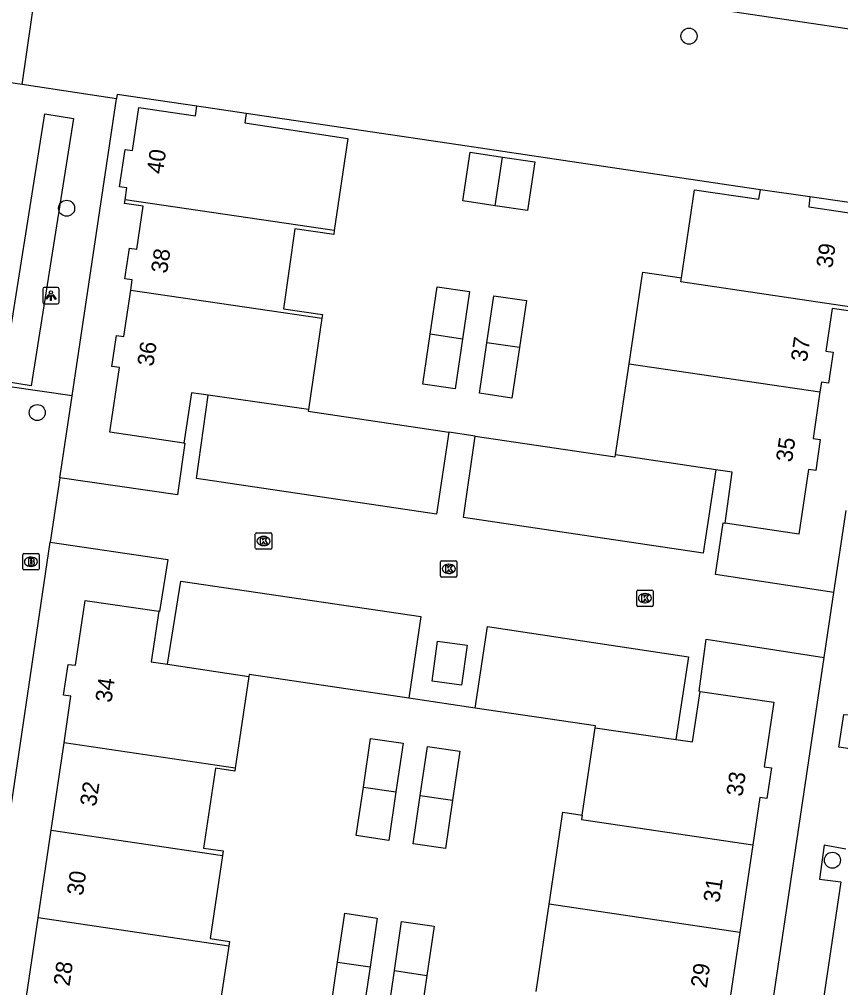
# Model space of a CAD drawing. Extents: x 164150 to 165261, y 382513 to 383432.
# Drawn here: x 164289.3 to 164339.4, y 382994.8 to 383053.9 of the extents above; entities that cross this region are included whole.
import ezdxf

# ---------------------------------------------------------------- set-up
doc = ezdxf.new("R2010")
doc.units = 0
for name, color, linetype in [('IMGEO_Boom', 7, 'Continuous'), ('IMGEO_Brandkraan', 7, 'Continuous'), ('IMGEO_Fietspad_gesloten', 7, 'Continuous'), ('IMGEO_Fietspad_open', 7, 'Continuous'), ('IMGEO_Groenvoorziening', 7, 'Continuous'), ('IMGEO_Kolk', 7, 'Continuous'), ('IMGEO_Lage_trafo', 7, 'Continuous'), ('IMGEO_Lichtpunt', 7, 'Continuous'), ('IMGEO_Pand', 7, 'Continuous'), ('IMGEO_Pand_nummerreeks', 7, 'Continuous'), ('IMGEO_Parkeervlak_open', 7, 'Continuous'), ('IMGEO_Rijbaan_lokaal_open', 7, 'Continuous'), ('IMGEO_Voetpad_open', 7, 'Continuous')]:
    doc.layers.add(name, color=color, linetype=linetype)

msp = doc.modelspace()

# ---------------------------------------------------------------- linework, layer by layer
at = {"layer": 'IMGEO_Boom'}
for centre in [(164330.143, 383052.86), (164292.167, 383042.363), (164290.373, 383029.895), (164338.896, 383002.583)]:
    msp.add_circle(centre, 0.489, dxfattribs=at)
at = {"layer": 'IMGEO_Brandkraan'}
for p, q in [((164289.488, 383020.369), (164289.488, 383021.221)), ((164289.563, 383021.295), (164290.415, 383021.295)), ((164289.976, 383021.075), (164290.001, 383021.075)), ((164290.489, 383021.221), (164290.489, 383020.369)), ((164290.415, 383020.295), (164289.563, 383020.295)), ((164289.999, 383020.515), (164289.974, 383020.515))]:
    msp.add_line(p, q, dxfattribs=at)
for points in [[(164289.488, 383020.369), (164289.488, 383021.221)], [(164289.563, 383021.295), (164290.415, 383021.295)], [(164289.836, 383020.995), (164289.836, 383020.595), (164290.049, 383020.595)], [(164290.067, 383020.995), (164289.836, 383020.995)], [(164290.015, 383020.914), (164289.961, 383020.914), (164289.961, 383020.838)], [(164290.489, 383021.221), (164290.489, 383020.369)], [(164290.415, 383020.295), (164289.563, 383020.295)], [(164289.961, 383020.838), (164290.014, 383020.838)], [(164290.023, 383020.762), (164289.961, 383020.762), (164289.961, 383020.681)], [(164289.961, 383020.681), (164290.023, 383020.681)]]:
    msp.add_lwpolyline(points, dxfattribs=at)
for centre, radius, start, end in [((164289.565, 383021.219), 0.0765, 91.55205, 178.44795), ((164289.565, 383021.219), 0.0765, 91.55205, 178.44795), ((164290.016, 383020.876), 0.0379, 267.82845, 90.93552), ((164290.071, 383020.85), 0.145, 59.4692, 91.53667), ((164290.096, 383020.897), 0.0922, 285.51372, 58.15012), ((164290.413, 383021.219), 0.0765, 1.55205, 88.44795), ((164290.413, 383021.219), 0.0765, 1.55205, 88.44795), ((164289.565, 383020.371), 0.0765, 181.55205, 268.44795), ((164289.565, 383020.371), 0.0765, 181.55205, 268.44795), ((164290.024, 383020.721), 0.0404, 269.87594, 90.50774), ((164290.055, 383020.846), 0.251, 268.66757, 293.53466), ((164290.101, 383020.705), 0.105, 301.31148, 78.98903), ((164290.413, 383020.371), 0.0765, 271.55205, 358.44795), ((164290.413, 383020.371), 0.0765, 271.55205, 358.44795)]:
    msp.add_arc(centre, radius, start, end, dxfattribs=at)
for centre, major_axis, ratio, start_param, end_param in [((164289.975, 383020.795), (-0.387, 0.002), 0.722429, 4.712389, 7.853982), ((164290, 383020.795), (-0.39, 0.002), 0.717154, 1.570796, 4.712389)]:
    msp.add_ellipse(centre, major_axis=major_axis, ratio=ratio, start_param=start_param, end_param=end_param, dxfattribs=at)
at = {"layer": 'IMGEO_Fietspad_gesloten'}
msp.add_lwpolyline([(164291.001, 383060.584), (164349.656, 383051.856)], dxfattribs=at)
at = {"layer": 'IMGEO_Fietspad_open'}
for points in [[(164289.455, 383049.901), (164290.642, 383058.11), (164290.645, 383058.127), (164291.001, 383060.584)], [(164289.455, 383049.901), (164287.476, 383050.195)]]:
    msp.add_lwpolyline(points, dxfattribs=at)
at = {"layer": 'IMGEO_Groenvoorziening'}
for points in [[(164300.119, 383048.586), (164295.247, 383049.303), (164295.212, 383049.069), (164295.209, 383049.046)], [(164334.498, 383043.494), (164333.125, 383043.698), (164321.502, 383045.42), (164316.052, 383046.228), (164303.121, 383048.144)], [(164342.411, 383042.068), (164342.452, 383042.342), (164337.518, 383043.057)]]:
    msp.add_lwpolyline(points, dxfattribs=at)
at = {"layer": 'IMGEO_Kolk'}
for p, q in [((164303.681, 383021.633), (164303.681, 383022.485)), ((164303.756, 383022.559), (164304.608, 383022.559)), ((164304.169, 383022.339), (164304.194, 383022.339)), ((164304.682, 383022.485), (164304.682, 383021.633)), ((164304.608, 383021.559), (164303.756, 383021.559)), ((164304.192, 383021.779), (164304.167, 383021.779)), ((164314.984, 383019.933), (164314.984, 383020.785)), ((164315.059, 383020.859), (164315.911, 383020.859)), ((164315.472, 383020.639), (164315.497, 383020.639)), ((164315.985, 383020.785), (164315.985, 383019.933)), ((164315.911, 383019.859), (164315.059, 383019.859)), ((164315.495, 383020.079), (164315.47, 383020.079)), ((164326.954, 383018.144), (164326.954, 383018.996)), ((164327.029, 383019.07), (164327.881, 383019.07)), ((164327.442, 383018.85), (164327.467, 383018.85)), ((164327.955, 383018.996), (164327.955, 383018.144)), ((164327.881, 383018.07), (164327.029, 383018.07)), ((164327.465, 383018.29), (164327.44, 383018.29))]:
    msp.add_line(p, q, dxfattribs=at)
for points in [[(164303.681, 383021.633), (164303.681, 383022.485)], [(164303.756, 383022.559), (164304.608, 383022.559)], [(164304.002, 383022.259), (164304.125, 383022.259), (164304.125, 383022.108), (164304.255, 383022.259), (164304.419, 383022.259), (164304.273, 383022.108), (164304.426, 383021.859), (164304.274, 383021.859), (164304.189, 383022.023), (164304.125, 383021.956), (164304.125, 383021.859), (164304.002, 383021.859), (164304.002, 383022.259)], [(164304.682, 383022.485), (164304.682, 383021.633)], [(164304.608, 383021.559), (164303.756, 383021.559)], [(164314.984, 383019.933), (164314.984, 383020.785)], [(164315.059, 383020.859), (164315.911, 383020.859)], [(164315.305, 383020.559), (164315.428, 383020.559), (164315.428, 383020.408), (164315.558, 383020.559), (164315.722, 383020.559), (164315.576, 383020.408), (164315.729, 383020.159), (164315.577, 383020.159), (164315.492, 383020.323), (164315.428, 383020.256), (164315.428, 383020.159), (164315.305, 383020.159), (164315.305, 383020.559)], [(164315.985, 383020.785), (164315.985, 383019.933)], [(164315.911, 383019.859), (164315.059, 383019.859)], [(164326.954, 383018.144), (164326.954, 383018.996)], [(164327.029, 383019.07), (164327.881, 383019.07)], [(164327.275, 383018.77), (164327.398, 383018.77), (164327.398, 383018.619), (164327.528, 383018.77), (164327.692, 383018.77), (164327.546, 383018.619), (164327.699, 383018.37), (164327.547, 383018.37), (164327.462, 383018.534), (164327.398, 383018.467), (164327.398, 383018.37), (164327.275, 383018.37), (164327.275, 383018.77)], [(164327.955, 383018.996), (164327.955, 383018.144)], [(164327.881, 383018.07), (164327.029, 383018.07)]]:
    msp.add_lwpolyline(points, dxfattribs=at)
for centre, start, end in [((164303.758, 383022.483), 91.55205, 178.44795), ((164303.758, 383022.483), 91.55205, 178.44795), ((164304.606, 383022.483), 1.55205, 88.44795), ((164304.606, 383022.483), 1.55205, 88.44795), ((164303.758, 383021.635), 181.55205, 268.44795), ((164303.758, 383021.635), 181.55205, 268.44795), ((164304.606, 383021.635), 271.55205, 358.44795), ((164304.606, 383021.635), 271.55205, 358.44795), ((164315.061, 383020.783), 91.55205, 178.44795), ((164315.061, 383020.783), 91.55205, 178.44795), ((164315.909, 383020.783), 1.55205, 88.44795), ((164315.909, 383020.783), 1.55205, 88.44795), ((164315.061, 383019.935), 181.55205, 268.44795), ((164315.061, 383019.935), 181.55205, 268.44795), ((164315.909, 383019.935), 271.55205, 358.44795), ((164315.909, 383019.935), 271.55205, 358.44795), ((164327.031, 383018.994), 91.55205, 178.44795), ((164327.031, 383018.994), 91.55205, 178.44795), ((164327.879, 383018.994), 1.55205, 88.44795), ((164327.879, 383018.994), 1.55205, 88.44795), ((164327.031, 383018.146), 181.55205, 268.44795), ((164327.031, 383018.146), 181.55205, 268.44795), ((164327.879, 383018.146), 271.55205, 358.44795), ((164327.879, 383018.146), 271.55205, 358.44795)]:
    msp.add_arc(centre, 0.0765, start, end, dxfattribs=at)
for centre, major_axis, ratio, start_param, end_param in [((164304.168, 383022.059), (-0.387, 0.002), 0.722429, 4.712389, 7.853982), ((164304.193, 383022.059), (-0.39, 0.002), 0.717154, 1.570796, 4.712389), ((164315.471, 383020.359), (-0.387, 0.002), 0.722429, 4.712389, 7.853982), ((164315.496, 383020.359), (-0.39, 0.002), 0.717154, 1.570796, 4.712389), ((164327.441, 383018.57), (-0.387, 0.002), 0.722429, 4.712389, 7.853982), ((164327.466, 383018.57), (-0.39, 0.002), 0.717154, 1.570796, 4.712389)]:
    msp.add_ellipse(centre, major_axis=major_axis, ratio=ratio, start_param=start_param, end_param=end_param, dxfattribs=at)
at = {"layer": 'IMGEO_Lage_trafo'}
msp.add_lwpolyline([(164314.788, 383015.944), (164316.601, 383015.698), (164316.264, 383013.265), (164314.465, 383013.51), (164314.788, 383015.944)], dxfattribs=at)
at = {"layer": 'IMGEO_Lichtpunt'}
for p, q in [((164290.708, 383037.431), (164290.708, 383036.624)), ((164290.708, 383037.431), (164290.708, 383036.624)), ((164291.61, 383037.526), (164290.802, 383037.526)), ((164291.61, 383037.526), (164290.802, 383037.526)), ((164291.704, 383036.624), (164291.704, 383037.431)), ((164291.704, 383036.624), (164291.704, 383037.431)), ((164290.802, 383036.53), (164291.61, 383036.53)), ((164290.802, 383036.53), (164291.61, 383036.53))]:
    msp.add_line(p, q, dxfattribs=at)
for points in [[(164291.082, 383037.095), (164291.121, 383037.067), (164290.933, 383036.805), (164290.895, 383036.832), (164291.082, 383037.095)], [(164291.184, 383037.047), (164291.231, 383037.047), (164291.231, 383036.725), (164291.184, 383036.725), (164291.184, 383037.047)], [(164291.294, 383037.067), (164291.332, 383037.094), (164291.519, 383036.832), (164291.48, 383036.804), (164291.294, 383037.067)]]:
    msp.add_lwpolyline(points, dxfattribs=at)
msp.add_circle((164291.207, 383037.229), 0.0994, dxfattribs=at)
for centre, start, end in [((164290.802, 383037.431), 90, 180), ((164290.802, 383037.431), 90, 180), ((164291.61, 383037.431), 0, 90), ((164291.61, 383037.431), 0, 90), ((164290.802, 383036.624), 180, 270), ((164290.802, 383036.624), 180, 270), ((164291.61, 383036.624), 270, 0), ((164291.61, 383036.624), 270, 360)]:
    msp.add_arc(centre, 0.0946, start, end, dxfattribs=at)
at = {"layer": 'IMGEO_Pand'}
for points in [[(164295.733, 383042.883), (164295.837, 383043.599), (164295.391, 383043.672), (164295.731, 383045.946), (164296.177, 383045.881), (164296.564, 383048.51), (164300.031, 383047.992), (164300.119, 383048.586)], [(164303.121, 383048.144), (164300.119, 383048.586)], [(164303.121, 383048.144), (164303.045, 383047.574), (164309.335, 383046.613), (164308.499, 383040.995)], [(164318.321, 383042.515), (164316.35, 383042.807), (164316.792, 383045.774), (164318.761, 383045.482)], [(164318.761, 383045.482), (164320.736, 383045.19), (164320.292, 383042.223), (164318.321, 383042.515)], [(164318.321, 383042.515), (164318.761, 383045.482)], [(164329.681, 383038.113), (164330.487, 383043.493), (164334.403, 383042.906), (164334.498, 383043.494)], [(164337.518, 383043.057), (164334.498, 383043.494)], [(164296.077, 383037.373), (164296.168, 383037.992), (164295.726, 383038.056), (164295.998, 383039.935), (164296.453, 383039.873), (164296.836, 383042.481), (164295.7, 383042.656), (164295.733, 383042.883)], [(164308.499, 383040.995), (164295.733, 383042.883)], [(164337.518, 383043.057), (164337.452, 383042.458), (164340.888, 383041.943), (164340.055, 383036.33)], [(164308.499, 383040.995), (164308.463, 383040.753), (164306.09, 383041.105), (164305.408, 383036.233), (164307.778, 383035.881), (164307.743, 383035.648)], [(164326.489, 383032.877), (164327.283, 383038.218), (164327.32, 383038.468), (164329.681, 383038.113)], [(164340.055, 383036.33), (164329.644, 383037.869), (164329.681, 383038.113)], [(164314.348, 383034.672), (164314.777, 383037.577), (164316.756, 383037.285), (164316.327, 383034.379)], [(164299.322, 383028.035), (164294.809, 383028.701), (164295.384, 383032.651), (164294.933, 383032.712), (164295.214, 383034.603), (164295.659, 383034.543), (164296.077, 383037.373)], [(164296.077, 383037.373), (164307.743, 383035.648)], [(164317.809, 383034.16), (164318.232, 383037.02), (164320.219, 383036.727), (164319.797, 383033.866)], [(164340.055, 383036.33), (164340.018, 383036.079), (164338.878, 383036.251), (164338.503, 383033.64), (164338.942, 383033.574), (164338.664, 383031.694), (164338.224, 383031.76), (164338.134, 383031.155)], [(164307.743, 383035.648), (164306.916, 383030.074)], [(164316.327, 383034.379), (164315.879, 383031.339), (164313.9, 383031.631), (164314.348, 383034.672)], [(164316.327, 383034.379), (164314.348, 383034.672)], [(164319.797, 383033.866), (164319.342, 383030.782), (164317.353, 383031.075), (164317.809, 383034.16)], [(164319.797, 383033.866), (164317.809, 383034.16)], [(164325.663, 383027.314), (164326.489, 383032.877)], [(164326.489, 383032.877), (164338.134, 383031.155)], [(164300.796, 383030.959), (164299.794, 383031.104), (164299.322, 383028.035)], [(164306.916, 383030.074), (164300.796, 383030.959)], [(164338.134, 383031.155), (164337.713, 383028.318), (164338.152, 383028.254), (164337.875, 383026.369), (164337.433, 383026.433), (164336.844, 383022.471), (164332.347, 383023.144)], [(164331.791, 383026.404), (164325.663, 383027.314)], [(164332.347, 383023.144), (164332.784, 383026.256), (164331.791, 383026.404)], [(164292.013, 383009.756), (164292.432, 383012.595), (164291.982, 383012.662), (164292.258, 383014.536), (164292.708, 383014.479), (164293.3, 383018.435), (164297.786, 383017.774)], [(164297.786, 383017.774), (164297.334, 383014.687), (164298.327, 383014.538)], [(164298.327, 383014.538), (164303.28, 383013.794)], [(164303.28, 383013.794), (164302.453, 383008.209)], [(164329.339, 383009.954), (164330.366, 383009.806), (164330.835, 383012.885)], [(164330.835, 383012.885), (164335.314, 383012.226), (164334.733, 383008.283), (164335.18, 383008.22), (164334.903, 383006.356), (164334.466, 383006.42), (164334.038, 383003.527)], [(164323.626, 383005.34), (164324.423, 383010.662)], [(164324.423, 383010.662), (164329.339, 383009.954)], [(164291.223, 383004.414), (164292.013, 383009.756)], [(164302.453, 383008.209), (164292.013, 383009.756)], [(164310.276, 383007.049), (164310.714, 383010.02), (164312.694, 383009.728), (164312.256, 383006.755)], [(164313.741, 383006.535), (164314.182, 383009.519), (164316.162, 383009.231), (164315.721, 383006.242)], [(164302.453, 383008.209), (164302.425, 383008.021), (164301.245, 383008.196), (164300.523, 383003.326), (164301.713, 383003.149), (164301.671, 383002.865)], [(164312.256, 383006.755), (164311.82, 383003.798), (164309.84, 383004.089), (164310.276, 383007.049)], [(164310.276, 383007.049), (164312.256, 383006.755)], [(164315.721, 383006.242), (164315.287, 383003.301), (164313.306, 383003.588), (164313.741, 383006.535)], [(164313.741, 383006.535), (164315.721, 383006.242)], [(164321.613, 382999.909), (164322.406, 383005.251), (164322.445, 383005.512), (164323.626, 383005.34)], [(164323.626, 383005.34), (164323.586, 383005.076), (164334.038, 383003.527)], [(164290.434, 382999.073), (164291.223, 383004.414)], [(164291.223, 383004.414), (164301.671, 383002.865)], [(164334.038, 383003.527), (164333.248, 382998.185)], [(164301.671, 383002.865), (164300.923, 382997.811), (164302.099, 382997.636), (164302.056, 382997.35)], [(164320.82, 382994.569), (164321.613, 382999.909)], [(164333.248, 382998.185), (164321.613, 382999.909)], [(164289.645, 382993.73), (164290.434, 382999.073)], [(164302.056, 382997.35), (164290.434, 382999.073)], [(164308.702, 382996.365), (164309.141, 382999.347), (164311.121, 382999.056), (164310.682, 382996.072)], [(164312.172, 382995.851), (164312.606, 382998.843), (164314.586, 382998.555), (164314.151, 382995.557)], [(164333.248, 382998.185), (164332.457, 382992.844)], [(164302.056, 382997.35), (164301.247, 382992.011)], [(164310.682, 382996.072), (164310.248, 382993.125), (164308.268, 382993.417), (164308.702, 382996.365)], [(164308.702, 382996.365), (164310.682, 382996.072)], [(164314.151, 382995.557), (164313.725, 382992.622), (164311.745, 382992.91), (164312.172, 382995.851)], [(164312.172, 382995.851), (164314.151, 382995.557)]]:
    msp.add_lwpolyline(points, dxfattribs=at)
at = {"layer": 'IMGEO_Parkeervlak_open'}
for points in [[(164306.916, 383030.074), (164306.902, 383029.983), (164315.481, 383028.705)], [(164317.098, 383028.465), (164325.645, 383027.192), (164325.663, 383027.314)], [(164313.051, 383012.471), (164303.299, 383013.923), (164303.28, 383013.794)], [(164324.423, 383010.662), (164324.44, 383010.776), (164317.096, 383011.869)]]:
    msp.add_lwpolyline(points, dxfattribs=at)
at = {"layer": 'IMGEO_Rijbaan_lokaal_open'}
for points in [[(164315.481, 383028.705), (164314.732, 383023.702), (164300.1, 383025.87), (164300.796, 383030.959)], [(164317.098, 383028.465), (164315.481, 383028.705)], [(164299.322, 383028.035), (164299.384, 383028.026), (164298.938, 383024.873), (164291.752, 383025.908)], [(164331.791, 383026.404), (164331.01, 383021.32), (164316.389, 383023.487), (164317.098, 383028.465)], [(164291.752, 383025.908), (164291.171, 383021.984)], [(164338.986, 383018.927), (164331.77, 383020.008), (164332.224, 383023.162), (164332.347, 383023.144)], [(164291.171, 383021.984), (164298.342, 383020.927), (164297.837, 383017.767), (164297.786, 383017.774)], [(164298.327, 383014.538), (164299.126, 383019.608), (164313.785, 383017.446), (164313.051, 383012.471)], [(164338.399, 383014.963), (164338.986, 383018.927)], [(164317.096, 383011.869), (164317.843, 383016.852), (164330.103, 383014.992), (164329.339, 383009.954)], [(164330.835, 383012.885), (164330.761, 383012.896), (164331.184, 383016.073), (164338.399, 383014.963)], [(164317.096, 383011.869), (164313.051, 383012.471)]]:
    msp.add_lwpolyline(points, dxfattribs=at)
at = {"layer": 'IMGEO_Voetpad_open'}
for points in [[(164295.209, 383049.046), (164289.455, 383049.901)], [(164292.499, 383030.912), (164295.209, 383049.046)], [(164290.83, 383048.121), (164292.587, 383047.843), (164290.009, 383031.53), (164288.253, 383031.807), (164290.83, 383048.121)], [(164292.499, 383030.912), (164279.108, 383032.842)], [(164291.752, 383025.908), (164291.869, 383026.7), (164292.499, 383030.912)], [(164338.986, 383018.927), (164339.726, 383023.927)], [(164278.188, 382934.213), (164291.171, 383021.984)], [(164325.346, 382927.185), (164331.117, 382966.047), (164338.115, 383013.045), (164338.399, 383014.963)], [(164340.219, 383009.345), (164339.289, 383009.488), (164339.592, 383011.483), (164340.728, 383011.393), (164340.486, 383009.67), (164340.219, 383009.345)], [(164339.705, 383003.262), (164338.398, 383003.496), (164338.099, 383001.43), (164339.408, 383001.26)], [(164339.408, 383001.26), (164338.026, 382991.946)]]:
    msp.add_lwpolyline(points, dxfattribs=at)

# ---------------------------------------------------------------- texts
at = {"layer": 'IMGEO_Pand_nummerreeks'}
for s, rotation, p in [('40', 81.49752, (164298.029, 383044.412)), ('38', 81.76108, (164298.294, 383038.352)), ('39', 81.56054, (164338.886, 383038.671)), ('37', 81.58919, (164337.334, 383032.952)), ('36', 81.54908, (164297.455, 383032.675)), ('35', 81.64076, (164336.428, 383026.835)), ('34', 81.59492, (164294.896, 383012.164)), ('33', 81.54908, (164333.399, 383006.438)), ('32', 81.59492, (164293.96, 383005.831)), ('30', 81.59492, (164293.156, 383000.388)), ('31', 81.58346, (164331.994, 382999.959)), ('28', 81.59492, (164292.34, 382994.865)), ('29', 81.58346, (164331.224, 382994.752))]:
    msp.add_text(s, height=1, rotation=rotation, dxfattribs=at).set_placement(p)

doc.saveas('drawing.dxf')
